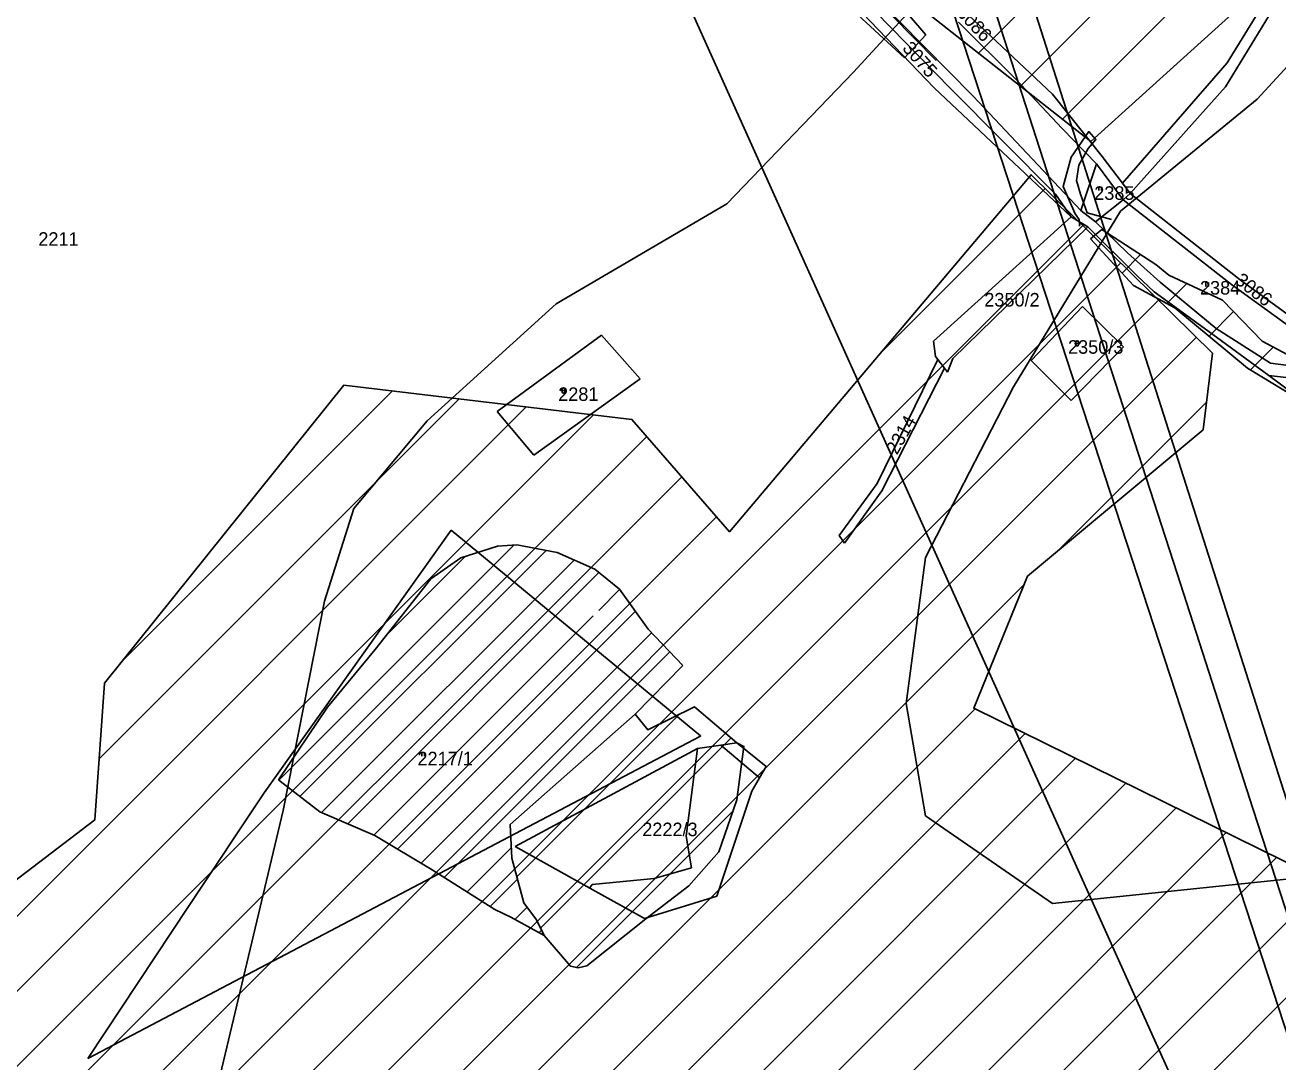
# Model space of a CAD drawing. Extents: x -564810 to -550519, y -1045831 to -1034011.
# Drawn here: x -552473.2 to -552001, y -1037786.6 to -1037395.7 of the extents above; entities that cross this region are included whole.
import ezdxf

# ---------------------------------------------------------------- set-up
doc = ezdxf.new("R2010")
doc.units = 0
for name, color, linetype in [('Interakční prvky', 7, 'Continuous'), ('KN stav', 7, 'Continuous'), ('Lesní porost', 7, 'Continuous'), ('Odvodněné plochy', 7, 'Continuous'), ('Parcelní čísla', 7, 'Continuous'), ('Polní cesty stavající', 7, 'Continuous'), ('přeložka st silnice', 7, 'Continuous'), ('STG', 7, 'Continuous'), ('Vedení VN', 7, 'Continuous'), ('Vrstva 14', 7, 'Continuous'), ('Vrstva 4', 7, 'Continuous'), ('zamokř ploch', 7, 'Continuous')]:
    doc.layers.add(name, color=color, linetype=linetype)

msp = doc.modelspace()

# ---------------------------------------------------------------- linework, layer by layer
at = {"layer": 'Interakční prvky'}
msp.add_lwpolyline([(-552462.58, -1037088.13), (-552332.15, -1037210.33), (-552245.52, -1037291.49), (-552129.73, -1037409.14)], dxfattribs=at)
at = {"layer": 'KN stav'}
for p, q in [((-552130.54, -1037419.33), (-552219.11, -1037326.9)), ((-552124.34, -1037419.63), (-552202.16, -1037340.08)), ((-551983.17, -1037357.5), (-552020.75, -1037418.97)), ((-551986.22, -1037355), (-552020.1, -1037409.91)), ((-552162.52, -1037375.17), (-552115.88, -1037422.58)), ((-552121.33, -1037394.7), (-552099.8, -1037416.12)), ((-552085.91, -1037421.82), (-552117.62, -1037391.97)), ((-552020.1, -1037409.91), (-552059.59, -1037455.35)), ((-552099.8, -1037416.12), (-552082.24, -1037434.76)), ((-552020.75, -1037418.97), (-552056.63, -1037459.25)), ((-552078.85, -1037468.02), (-552130.54, -1037419.33)), ((-552084.78, -1037459.43), (-552124.34, -1037419.63)), ((-552115.88, -1037422.58), (-552075.24, -1037465.69)), ((-552067.28, -1037445.27), (-552085.91, -1037421.82)), ((-552082.24, -1037434.76), (-552069.36, -1037448.03)), ((-552067.28, -1037445.27), (-552059.59, -1037455.35)), ((-552069.36, -1037448.03), (-552075.24, -1037465.69)), ((-552069.36, -1037448.03), (-552059.33, -1037461.62)), ((-552059.59, -1037455.35), (-552056.63, -1037459.25)), ((-552078.85, -1037468.02), (-552084.78, -1037459.43)), ((-552056.63, -1037459.25), (-552059.33, -1037461.62)), ((-552056.63, -1037459.25), (-552015.17, -1037491.75)), ((-552075.24, -1037465.69), (-552069.76, -1037469.89)), ((-552059.33, -1037461.62), (-552069.76, -1037469.89)), ((-552059.33, -1037461.62), (-552018.5, -1037493.58)), ((-552130.77, -1037514.92), (-552078.85, -1037468.02)), ((-552072.62, -1037471.76), (-552078.85, -1037468.02)), ((-552069.76, -1037469.89), (-552057.71, -1037481.57)), ((-552072.62, -1037471.76), (-552123.56, -1037521.37)), ((-552054.2, -1037490.12), (-552072.62, -1037471.76)), ((-552057.71, -1037481.57), (-552045.36, -1037492.62)), ((-552047.61, -1037496.3), (-552054.2, -1037490.12)), ((-552045.36, -1037492.62), (-552024.3, -1037510.11)), ((-552018.5, -1037493.58), (-551975.61, -1037524.72)), ((-552015.17, -1037491.75), (-551982.62, -1037515.54)), ((-552027.44, -1037511.05), (-552047.61, -1037496.3)), ((-552093.98, -1037522.24), (-552074.63, -1037501.82)), ((-552074.63, -1037501.82), (-552059.18, -1037517.01)), ((-552295.27, -1037541.44), (-552255.91, -1037512.64)), ((-552255.91, -1037512.64), (-552241.35, -1037529.09)), ((-552004.36, -1037527.84), (-552027.44, -1037511.05)), ((-552024.3, -1037510.11), (-552003.81, -1037523.18)), ((-552130.02, -1037520.63), (-552130.77, -1037514.92)), ((-552059.18, -1037517.01), (-552078.86, -1037537.31)), ((-552152.04, -1037568.49), (-552129.1, -1037521.82)), ((-552129.1, -1037521.82), (-552130.02, -1037520.63)), ((-552129.1, -1037521.82), (-552126.59, -1037525.09)), ((-552123.56, -1037521.37), (-552125.47, -1037526.56)), ((-552078.86, -1037537.31), (-552093.98, -1037522.24)), ((-552126.59, -1037525.09), (-552150.24, -1037571.25)), ((-552125.47, -1037526.56), (-552126.59, -1037525.09)), ((-552003.81, -1037523.18), (-551972.96, -1037527.06)), ((-552241.35, -1037529.09), (-552281.37, -1037557.83)), ((-551973.47, -1037531.4), (-552004.36, -1037527.84)), ((-551987.25, -1037540.65), (-552004.36, -1037527.84)), ((-552281.37, -1037557.83), (-552295.27, -1037541.44)), ((-552166.33, -1037588.18), (-552152.04, -1037568.49)), ((-552150.24, -1037571.25), (-552164.32, -1037591.04)), ((-552383.1, -1037685.13), (-552312.51, -1037586.17)), ((-552312.51, -1037586.17), (-552218.57, -1037663.73)), ((-552164.32, -1037591.04), (-552166.33, -1037588.18)), ((-552218.58, -1037663.74), (-552449.55, -1037785.31)), ((-552218.57, -1037663.73), (-552218.58, -1037663.74)), ((-552219.71, -1037668.43), (-552288.49, -1037705.41)), ((-552219.71, -1037668.43), (-552210.99, -1037667.15)), ((-552204.86, -1037666.25), (-552210.99, -1037667.15)), ((-552193.9, -1037675.21), (-552204.86, -1037666.25)), ((-552196.31, -1037679.46), (-552193.9, -1037675.21)), ((-552199.21, -1037684.58), (-552196.31, -1037679.46)), ((-552411.56, -1037728.04), (-552383.1, -1037685.13)), ((-552212.42, -1037724.1), (-552199.21, -1037684.58)), ((-552288.49, -1037705.41), (-552260.36, -1037721.08)), ((-552260.36, -1037721.08), (-552239.71, -1037732.59)), ((-552239.71, -1037732.59), (-552212.42, -1037724.1)), ((-552449.55, -1037785.31), (-552411.56, -1037728.04))]:
    msp.add_line(p, q, dxfattribs=at)
at = {"layer": 'Lesní porost'}
for p, q in [((-552133.64, -1037399.36), (-552149.54, -1037380.89)), ((-552164.26, -1037387.31), (-552141.75, -1037408.11)), ((-552141.75, -1037408.11), (-552133.64, -1037399.36)), ((-552067.35, -1037472.8), (-552071.58, -1037476.32)), ((-552046.97, -1037485.98), (-552067.35, -1037472.8)), ((-552071.58, -1037476.32), (-552055.44, -1037493.89)), ((-552059.72, -1037489.23), (-552052.74, -1037482.25)), ((-552042.13, -1037489.96), (-552046.97, -1037485.98)), ((-552055.44, -1037493.89), (-552039.84, -1037502.29)), ((-552042.86, -1037500.66), (-552035.33, -1037493.13)), ((-552021.86, -1037499.4), (-552042.13, -1037489.96)), ((-552039.84, -1037502.29), (-552012.49, -1037525.04)), ((-552026.94, -1037513.02), (-552017.67, -1037503.75)), ((-552006.93, -1037514.9), (-552021.86, -1037499.4)), ((-552011.36, -1037525.73), (-552002.75, -1037517.12)), ((-551993.53, -1037522.03), (-552006.93, -1037514.9)), ((-552012.49, -1037525.04), (-551993.97, -1037536.29)), ((-552287.82, -1037716.84), (-552226.6, -1037655.62)), ((-552278.85, -1037736.15), (-552207.08, -1037664.38)), ((-552265.37, -1037750.95), (-552206.34, -1037691.93))]:
    msp.add_line(p, q, dxfattribs=at)
msp.add_lwpolyline([(-552290.37, -1037697.13), (-552289.71, -1037709.74), (-552285.23, -1037726.57), (-552280.4, -1037733.05), (-552277.48, -1037738.88), (-552267.6, -1037750.44), (-552264.73, -1037751.1), (-552261.44, -1037750.33), (-552239.23, -1037732.64), (-552223.02, -1037720.21), (-552211.68, -1037707.45), (-552204.91, -1037687.77), (-552202.24, -1037667.68), (-552204.86, -1037666.25), (-552220.86, -1037652.79), (-552238.4, -1037661.43), (-552243.19, -1037655.5)], close=True, dxfattribs=at)
at = {"layer": 'Odvodněné plochy'}
for points in [[(-552014.39, -1037387.96), (-552071.44, -1037439.67), (-552181.86, -1037352.69)], [(-552733.97, -1038945.29), (-552767.09, -1038873.49), (-552908.8, -1038796.18), (-552949.29, -1038879.02), (-552998.98, -1038862.45), (-553032.11, -1038794.34), (-552991.62, -1038575.28), (-552918, -1038424.33), (-552706.36, -1038183.18), (-552594.1, -1037807.66), (-552446.87, -1037695.36), (-552443.19, -1037643.82), (-552353.02, -1037531.53), (-552244.44, -1037544.42), (-552207.63, -1037586.76), (-552094.02, -1037452.14), (-552025.64, -1037519.39), (-552029.11, -1037548.28), (-552095.37, -1037603.51), (-552115.61, -1037653.21), (-551981.27, -1037719.48)]]:
    msp.add_lwpolyline(points, dxfattribs=at)
at = {"layer": 'Polní cesty stavající'}
msp.add_lwpolyline([(-552075.73, -1037471.56), (-552075.86, -1037469.03), (-552077.41, -1037466.86), (-552081.96, -1037456.56), (-552078.86, -1037445.47), (-552072.29, -1037435.87), (-552069.58, -1037438.88), (-552072.45, -1037442.22), (-552076.02, -1037448.59), (-552076.83, -1037454.31), (-552075.43, -1037459.43), (-552072.9, -1037466.48), (-552063.68, -1037469.08)], dxfattribs=at)
at = {"layer": 'přeložka st silnice'}
for p, q in [((-552113.84, -1037406.28), (-551875.08, -1037167.52)), ((-552098.02, -1037418.74), (-551896.99, -1037217.72)), ((-552082.2, -1037431.2), (-551971.61, -1037320.62)), ((-552150.64, -1037519.23), (-552088.74, -1037457.33)), ((-552672.27, -1038069.15), (-552074.48, -1037471.35)), ((-552684.33, -1038109.49), (-552060.22, -1037485.38)), ((-552696.39, -1038149.84), (-552045.96, -1037499.4)), ((-552741.55, -1038223.28), (-552031.7, -1037513.43)), ((-552445.23, -1037672.4), (-552309.52, -1037536.69)), ((-552436.08, -1037634.97), (-552334.81, -1037533.69)), ((-552611.97, -1037867.42), (-552284.24, -1037539.69)), ((-552084.13, -1037594.14), (-552027.86, -1037537.87)), ((-552624.03, -1037907.77), (-552258.96, -1037542.69)), ((-552636.09, -1037948.11), (-552238.84, -1037550.86)), ((-552648.15, -1037988.46), (-552225.68, -1037565.99)), ((-552660.21, -1038028.8), (-552212.53, -1037581.12)), ((-552921.51, -1038431.52), (-552096.65, -1037606.66)), ((-553031.34, -1038795.91), (-551867.4, -1037631.97)), ((-552948.43, -1038486.73), (-552115.14, -1037653.44)), ((-552975.36, -1038541.94), (-552096.2, -1037662.78)), ((-552994.16, -1038589.02), (-552077.26, -1037672.13)), ((-553000.57, -1038623.72), (-552058.32, -1037681.47)), ((-553006.98, -1038658.42), (-552039.38, -1037690.81)), ((-553013.4, -1038693.11), (-552020.44, -1037700.16)), ((-553019.81, -1038727.81), (-552001.5, -1037709.5)), ((-553026.22, -1038762.51), (-551982.56, -1037718.84))]:
    msp.add_line(p, q, dxfattribs=at)
at = {"layer": 'STG'}
for points in [[(-552408.94, -1037830.61), (-552375.87, -1037691.87), (-552360.25, -1037612.86), (-552349.23, -1037577.94), (-552321.67, -1037544.87), (-552272.99, -1037500.76), (-552208.69, -1037463.09), (-552160.93, -1037413.48), (-552004.78, -1037243.5), (-551961.6, -1037184.7)], [(-551968.4, -1037379.58), (-552008.82, -1037423.68), (-552060.26, -1037465.94), (-552100.67, -1037532.1), (-552133.74, -1037596.41), (-552141.09, -1037651.54), (-552133.74, -1037693.8), (-552085.98, -1037726.88), (-551997.79, -1037717.69)]]:
    msp.add_lwpolyline(points, dxfattribs=at)
at = {"layer": 'Vedení VN'}
for points in [[(-552432.62, -1036280.68), (-552381.75, -1036354.88), (-552340.78, -1036472.89), (-552289.91, -1036771.81), (-551953.63, -1037825.94), (-551890.75, -1037944.66), (-551680.22, -1038317.07)], [(-551695.24, -1038326.94), (-551700.71, -1038330.65), (-551972.06, -1037853.73), (-552325.94, -1036770.4), (-552370.45, -1036480.66), (-552411.81, -1036369.59), (-552471.47, -1036287.75)], [(-552068.06, -1037512.55), (-552118.7, -1037355.64), (-552166.52, -1037207.15), (-552210.92, -1037069.77), (-552249.26, -1036951.7), (-552280.11, -1036856.27), (-552310.82, -1036764.06)], [(-551691.6, -1038324.25), (-551753.32, -1038215.22), (-551815.56, -1038104.9), (-551888.03, -1037977.11), (-551957.29, -1037854.44), (-552010.26, -1037691.39), (-552038.99, -1037602.42), (-552068.06, -1037512.55)]]:
    msp.add_lwpolyline(points, dxfattribs=at)
at = {"layer": 'Vrstva 14'}
msp.add_lwpolyline([(-551754.89, -1038428.38), (-553519.59, -1034507.17), (-553502.09, -1034572.44)], dxfattribs=at)
at = {"layer": 'Vrstva 4'}
for p, q in [((-552219.71, -1037668.43), (-552223.94, -1037701.49)), ((-552196.31, -1037679.46), (-552210.99, -1037667.15)), ((-552223.94, -1037701.49), (-552222.05, -1037713.43)), ((-552222.05, -1037713.43), (-552236.04, -1037717.41)), ((-552259.48, -1037719.65), (-552260.37, -1037721.08)), ((-552236.04, -1037717.41), (-552259.48, -1037719.65))]:
    msp.add_line(p, q, dxfattribs=at)
at = {"layer": 'zamokř ploch'}
for p, q in [((-552068.46, -1037456.65), (-552068.46, -1037458.15)), ((-552067.46, -1037456.65), (-552067.46, -1037458.15)), ((-552028.16, -1037492.76), (-552028.16, -1037494.26)), ((-552027.16, -1037492.76), (-552027.16, -1037494.26)), ((-552077.61, -1037515.72), (-552075.61, -1037515.72)), ((-552077.11, -1037516.22), (-552077.11, -1037515.22)), ((-552076.11, -1037515.22), (-552076.11, -1037516.22)), ((-552271.19, -1037533.53), (-552269.19, -1037533.53)), ((-552270.69, -1037534.03), (-552270.69, -1037533.03)), ((-552269.69, -1037533.03), (-552269.69, -1037534.03)), ((-552377.49, -1037680.34), (-552288.86, -1037591.71)), ((-552369.57, -1037686.56), (-552276.77, -1037593.76)), ((-552295.1, -1037592.18), (-552308.86, -1037596.61)), ((-552287.77, -1037591.63), (-552295.1, -1037592.18)), ((-552272.64, -1037594.56), (-552287.77, -1037591.63)), ((-552361.43, -1037692.56), (-552266.25, -1037597.39)), ((-552336.98, -1037625.68), (-552307.45, -1037596.15)), ((-552308.86, -1037596.61), (-552320.26, -1037604.48)), ((-552258.44, -1037600.85), (-552272.64, -1037594.56)), ((-552351.55, -1037696.83), (-552256.86, -1037602.14)), ((-552249.16, -1037608.4), (-552258.44, -1037600.85)), ((-552320.26, -1037604.48), (-552341.26, -1037631.12)), ((-552256.96, -1037616.38), (-552249.08, -1037608.5)), ((-552238.38, -1037623.45), (-552249.16, -1037608.4)), ((-552332.78, -1037706.34), (-552243.18, -1037616.74)), ((-552341.68, -1037701.1), (-552259, -1037618.42)), ((-552323.93, -1037711.63), (-552237.09, -1037624.79)), ((-552225.2, -1037637.11), (-552238.38, -1037623.45)), ((-552341.26, -1037631.12), (-552359.22, -1037652.83)), ((-552315.18, -1037717.02), (-552230.14, -1037631.99)), ((-552243.19, -1037655.5), (-552225.2, -1037637.11)), ((-552359.22, -1037652.83), (-552377.59, -1037680.26)), ((-552290.37, -1037697.13), (-552243.19, -1037655.5)), ((-552323.6, -1037669.83), (-552323.6, -1037671.33)), ((-552322.6, -1037669.83), (-552322.6, -1037671.33)), ((-552377.59, -1037680.26), (-552375.93, -1037681.7)), ((-552375.93, -1037681.7), (-552362.08, -1037692.28)), ((-552362.08, -1037692.28), (-552341.27, -1037701.27)), ((-552289.71, -1037709.74), (-552290.37, -1037697.13)), ((-552341.27, -1037701.27), (-552319.71, -1037714.15)), ((-552306.52, -1037722.51), (-552289.91, -1037705.9)), ((-552285.23, -1037726.57), (-552289.71, -1037709.74)), ((-552319.71, -1037714.15), (-552296.14, -1037729.1)), ((-552297.87, -1037728), (-552287.59, -1037717.72)), ((-552296.14, -1037729.1), (-552290.13, -1037732.08)), ((-552288.62, -1037732.89), (-552283.98, -1037728.25)), ((-552280.4, -1037733.05), (-552285.23, -1037726.57)), ((-552290.13, -1037732.08), (-552277.48, -1037738.88)), ((-552277.48, -1037738.88), (-552280.4, -1037733.05)), ((-552279.42, -1037737.84), (-552278.48, -1037736.89))]:
    msp.add_line(p, q, dxfattribs=at)
for centre, start, end in [((-552076.61, -1037515.22), 0, 180), ((-552076.61, -1037516.22), 180, 0), ((-552270.19, -1037533.03), 0, 180), ((-552270.19, -1037534.03), 180, 0)]:
    msp.add_arc(centre, 0.5, start, end, dxfattribs=at)

# ---------------------------------------------------------------- texts
at = {"layer": 'Parcelní čísla'}
for s, rotation, p in [('3086', 312.9911, (-552122.4, -1037391.39)), ('3075', 311.9002, (-552142.82, -1037404.69)), ('3086', 321.6944, (-552017.55, -1037492.73)), ('2314', 60.6113, (-552144.55, -1037558.02))]:
    msp.add_text(s, height=5.1, rotation=rotation, dxfattribs=at).set_placement(p)
for s, p in [('2385', (-552070.2, -1037461.62)), ('2211', (-552468.15, -1037478.93)), ('2384', (-552030.36, -1037497.33)), ('2350/2', (-552111.64, -1037501.83)), ('2350/3', (-552080.09, -1037519.63)), ('2281', (-552272.23, -1037537.42)), ('2217/1', (-552325.25, -1037674.79)), ('2222/3', (-552240.55, -1037701.49))]:
    msp.add_text(s, height=5.1, dxfattribs=at).set_placement(p)

doc.saveas('drawing.dxf')
